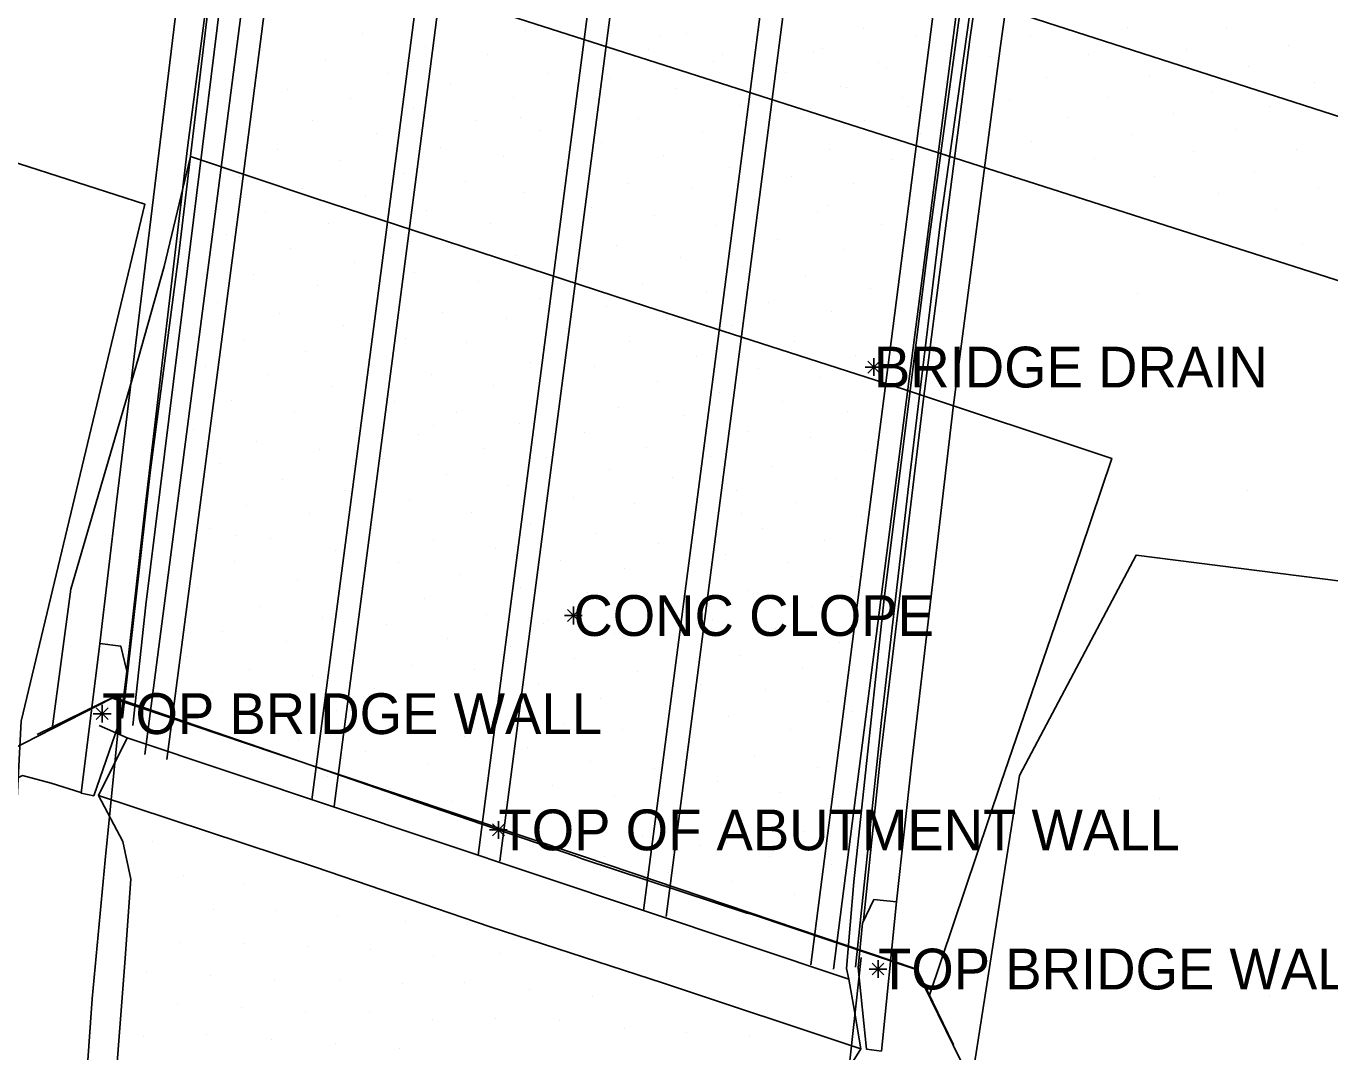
# Model space of a CAD drawing. Extents: x 1733582 to 1734070, y 467256 to 468256.
# Drawn here: x 1733813.9 to 1733871.5, y 467649 to 467694.3 of the extents above; entities that cross this region are included whole.
import ezdxf

# ---------------------------------------------------------------- set-up
doc = ezdxf.new("R2010")
doc.units = 0
for name, color, linetype in [('Default', 7, 'Continuous'), ('S_Bridge_Abutment_Bottom', 7, 'Continuous'), ('S_Bridge_Curb', 7, 'Continuous'), ('S_Bridge_Deck', 7, 'Continuous'), ('S_Bridge_ExpansionJoint', 7, 'Continuous'), ('S_Bridge_Parapet', 7, 'Continuous'), ('S_Bridge_Rail', 7, 'Continuous'), ('S_Bridge_Wingwall', 7, 'Continuous'), ('S_Ground_LevelString', 7, 'Continuous'), ('S_Ground_SpotElevation', 7, 'Continuous'), ('S_Guardrail_Beam', 7, 'Continuous'), ('S_Misc_MiscFeature', 7, 'Continuous'), ('S_Misc_MiscItems', 7, 'Continuous'), ('S_Roadway_Edge_Pavement', 7, 'Continuous'), ('S_Roadway_Painted_Lines', 7, 'Continuous'), ('S_Text', 7, 'Continuous'), ('S_Trees_Bush_Line', 7, 'Continuous')]:
    doc.layers.add(name, color=color, linetype=linetype)

# ---------------------------------------------------------------- blocks, each defined once
blk = doc.blocks.new('POINT_DISPLAY')
at = {"layer": 'Default'}
blk.add_line((0, 0), (0, 0), dxfattribs=at)

msp = doc.modelspace()

# ---------------------------------------------------------------- linework, layer by layer
at = {"layer": 'S_Bridge_Abutment_Bottom'}
for points in [[(1733853.787, 467651.451), (1733856.947, 467660.863), (1733859.499, 467668.329), (1733860.465, 467671.091), (1733861.843, 467675.202), (1733852.689, 467678.242), (1733841.297, 467681.912), (1733826.618, 467686.702), (1733821.169, 467688.527), (1733820, 467683.677), (1733818.858, 467679.602), (1733815.879, 467669.434), (1733815.061, 467663.265)], [(1733856.158, 467646.59), (1733853.195, 467652.663), (1733838.519, 467657.625), (1733824.913, 467662.193), (1733817.71, 467664.62), (1733811.826, 467661.611)]]:
    msp.add_lwpolyline(points, dxfattribs=at)
at = {"layer": 'S_Bridge_Curb'}
for points in [[(1733818.159, 467663.732), (1733819.385, 467674.582), (1733820.64, 467684.116), (1733822.243, 467697.564), (1733823.972, 467709.579), (1733825.87, 467722.342), (1733827.859, 467734.138), (1733830.216, 467748.192), (1733832.11, 467758.256), (1733834.51, 467770.45), (1733837.898, 467787.063), (1733840.865, 467800.549), (1733844.359, 467815.787), (1733847.831, 467829.289), (1733850.56, 467839.861), (1733853.05, 467849.061), (1733854.563, 467854.584)], [(1733850.525, 467652.736), (1733851.676, 467663.636), (1733852.883, 467674.082), (1733854.262, 467685.548), (1733855.565, 467694.75), (1733856.845, 467703.748), (1733858.974, 467717.399), (1733861.233, 467731.524), (1733863.482, 467743.881), (1733865.283, 467752.922), (1733867.113, 467762.582), (1733868.83, 467770.933), (1733871.654, 467784.015), (1733874.05, 467794.414), (1733876.107, 467803.265), (1733877.952, 467810.863), (1733879.709, 467817.89), (1733881.379, 467824.23), (1733883.522, 467832.303), (1733885.6, 467839.734), (1733886.897, 467844.023)]]:
    msp.add_lwpolyline(points, dxfattribs=at)
at = {"layer": 'S_Bridge_Deck'}
msp.add_line((1733817.139, 467663.409), (1733818.374, 467662.864), dxfattribs=at)
for points in [[(1733855.138, 467854.785), (1733853.086, 467847.693), (1733849.22, 467833.073), (1733845.482, 467818.291), (1733842.048, 467803.532), (1733838.704, 467788.663), (1733835.558, 467773.547), (1733832.728, 467759.072), (1733829.896, 467743.681), (1733827.379, 467728.743), (1733824.957, 467713.563), (1733822.869, 467698.529), (1733821.029, 467683.583), (1733819.201, 467668.729), (1733818.621, 467663.409)], [(1733886.549, 467844.629), (1733884.683, 467838.178), (1733882.551, 467830.444), (1733878.067, 467813.135), (1733874.221, 467797.292), (1733871.125, 467783.729), (1733866.753, 467762.871), (1733863.994, 467749.165), (1733860.716, 467731.07), (1733858.373, 467716.77), (1733855.935, 467700.728), (1733853.766, 467684.771), (1733851.796, 467669.015), (1733850.46, 467656.5), (1733850.135, 467652.683), (1733850.236, 467652.213)]]:
    msp.add_lwpolyline(points, dxfattribs=at)
at = {"layer": 'S_Bridge_ExpansionJoint'}
for points in [[(1733850.236, 467652.213), (1733818.374, 467662.864), (1733817.11, 467660.315), (1733826.68, 467657.156), (1733834.4, 467654.523), (1733842.051, 467652.036), (1733850.758, 467649.134), (1733850.483, 467650.79), (1733850.236, 467652.213)], [(1733817.11, 467660.315), (1733826.68, 467657.156), (1733834.4, 467654.523), (1733842.051, 467652.036), (1733850.758, 467649.134)]]:
    msp.add_lwpolyline(points, dxfattribs=at)
at = {"layer": 'S_Bridge_Parapet'}
for points in [[(1733816.907, 467660.305), (1733818.113, 467663.794), (1733818.35, 467665.811), (1733818.091, 467666.911), (1733817.169, 467667.027), (1733816.348, 467660.418), (1733816.907, 467660.305)], [(1733852.333, 467655.629), (1733851.341, 467655.722), (1733850.84, 467654.678), (1733850.65, 467652.713), (1733851.016, 467649.11), (1733851.669, 467649.029), (1733852.333, 467655.629)]]:
    msp.add_lwpolyline(points, dxfattribs=at)
at = {"layer": 'S_Bridge_Rail'}
for points in [[(1733818.359, 467665.855), (1733819.171, 467673.048), (1733821.039, 467688.917), (1733823.113, 467704.785), (1733825.46, 467720.602), (1733828.058, 467736.434), (1733830.845, 467752.168), (1733833.805, 467767.85), (1733837.016, 467783.594), (1733840.405, 467799.172), (1733844.065, 467814.724), (1733847.908, 467830.326), (1733851.933, 467845.769), (1733853.853, 467852.641)], [(1733886.303, 467841.899), (1733884.339, 467834.722), (1733880.236, 467819.247), (1733876.383, 467803.848), (1733872.741, 467788.157), (1733869.344, 467772.479), (1733866.194, 467756.807), (1733863.147, 467741.167), (1733860.402, 467725.353), (1733857.873, 467709.488), (1733855.573, 467693.7), (1733853.508, 467677.718), (1733851.616, 467661.907), (1733850.883, 467654.795)]]:
    msp.add_lwpolyline(points, dxfattribs=at)
at = {"layer": 'S_Bridge_Wingwall'}
msp.add_lwpolyline([(1733816.328, 467660.448), (1733815.01, 467660.86), (1733813.747, 467661.195), (1733812.317, 467660.528)], dxfattribs=at)
at = {"layer": 'S_Ground_LevelString'}
msp.add_lwpolyline([(1733853.787, 467651.451), (1733856.947, 467660.863), (1733859.499, 467668.329), (1733860.465, 467671.091), (1733861.843, 467675.202), (1733852.689, 467678.242), (1733841.297, 467681.912), (1733826.618, 467686.702), (1733821.169, 467688.527), (1733820, 467683.677), (1733818.858, 467679.602), (1733815.879, 467669.434), (1733815.061, 467663.265)], dxfattribs=at)
at = {"layer": 'S_Guardrail_Beam'}
for points in [[(1733807.383, 467564.54), (1733809.319, 467567.868), (1733810.292, 467569.832), (1733810.683, 467571.034), (1733811.12, 467573.524), (1733811.405, 467576.28), (1733812.386, 467588.95), (1733813.146, 467601.374), (1733813.995, 467613.961), (1733814.875, 467626.317), (1733815.844, 467638.741), (1733816.383, 467645.072), (1733816.822, 467651.337), (1733817.407, 467657.46), (1733818.079, 467664.272)], [(1733850.774, 467653.171), (1733849.7, 467643.369), (1733849.038, 467637.329), (1733848.501, 467631.188), (1733847.844, 467621.901), (1733847.266, 467609.259), (1733846.773, 467596.932), (1733846.395, 467584.271), (1733846.161, 467571.826), (1733846.092, 467559.57), (1733846.114, 467553.099), (1733846.071, 467546.973), (1733846.619, 467534.281), (1733847.23, 467525.758), (1733848.03, 467521.946), (1733848.441, 467520.58), (1733850.4, 467515.952)]]:
    msp.add_lwpolyline(points, dxfattribs=at)
at = {"layer": 'S_Misc_MiscFeature'}
for points in [[(1733819.146, 467662.128), (1733822.411, 467687.138), (1733825.625, 467712.064), (1733828.308, 467732.621), (1733831.184, 467747.947), (1733833.505, 467760.094), (1733835.806, 467771.99), (1733838.257, 467784.633), (1733839.477, 467789.916), (1733843.642, 467806.605), (1733849.69, 467830.62), (1733855.796, 467855.018)], [(1733820.122, 467661.91), (1733823.472, 467687.541), (1733826.672, 467712.367), (1733829.355, 467732.542), (1733832.44, 467748.988), (1733834.659, 467760.701), (1733836.916, 467772.404), (1733839.778, 467786.991), (1733844.946, 467807.685), (1733851.172, 467832.455), (1733856.733, 467854.727)], [(1733826.53, 467660.119), (1733830.278, 467688.775), (1733833.202, 467711.396), (1733835.635, 467730.109), (1733838.854, 467747.125), (1733841.053, 467758.65), (1733843.35, 467770.62), (1733845.821, 467783.336), (1733847.212, 467789.204), (1733851.47, 467806.186), (1733857.516, 467830.268), (1733863.15, 467852.64)], [(1733864.079, 467852.275), (1733858.131, 467828.607), (1733852.049, 467804.339), (1733847.192, 467785.066), (1733844.207, 467769.696), (1733841.988, 467758.102), (1733839.394, 467744.549), (1733836.696, 467730.312), (1733833.835, 467708.583), (1733831.31, 467688.992), (1733827.509, 467659.844)], [(1733852.432, 467852.088), (1733847.956, 467835.582), (1733844.668, 467822.664), (1733840.962, 467807.205), (1733837.376, 467791.545), (1733834.11, 467775.918), (1733831.093, 467760.248), (1733828.17, 467744.438), (1733825.424, 467728.718), (1733822.802, 467711.353), (1733820.741, 467696.705), (1733817.897, 467673.275), (1733817.169, 467667.027)], [(1733833.862, 467657.682), (1733837.178, 467683.156), (1733840.254, 467706.86), (1733843.003, 467727.895), (1733846.149, 467744.535), (1733848.346, 467756.071), (1733850.647, 467768.07), (1733853.573, 467783.047), (1733858.608, 467802.95), (1733864.671, 467827.038), (1733870.472, 467850.181)], [(1733871.393, 467849.822), (1733865.695, 467826.963), (1733859.504, 467802.42), (1733854.508, 467782.647), (1733851.621, 467767.768), (1733849.286, 467755.703), (1733847.085, 467744.185), (1733843.99, 467727.733), (1733841.143, 467705.862), (1733838.187, 467683.149), (1733834.828, 467657.424)], [(1733841.162, 467655.238), (1733844.601, 467681.503), (1733847.732, 467705.748), (1733850.338, 467725.565), (1733853.469, 467742.079), (1733855.705, 467753.836), (1733857.987, 467765.604), (1733860.885, 467780.409), (1733865.914, 467800.487), (1733872.136, 467825.216), (1733877.778, 467847.684)], [(1733878.753, 467847.484), (1733873.086, 467824.941), (1733866.9, 467800.334), (1733861.829, 467780.055), (1733858.912, 467765.093), (1733856.608, 467753.207), (1733854.359, 467741.368), (1733851.322, 467725.26), (1733848.676, 467705.17), (1733845.544, 467680.934), (1733842.168, 467654.979)], [(1733848.559, 467652.836), (1733852.024, 467679.791), (1733855.066, 467703.463), (1733857.598, 467722.922), (1733860.883, 467740.131), (1733863.02, 467751.281), (1733865.314, 467763.253), (1733868.31, 467778.566), (1733873.148, 467797.76), (1733879.142, 467821.53), (1733885.249, 467845.685)], [(1733849.555, 467652.651), (1733852.726, 467677.347), (1733855.925, 467702.233), (1733858.601, 467722.747), (1733863.855, 467750.228), (1733866.106, 467762.026), (1733869.19, 467777.948), (1733873.963, 467796.905), (1733880.016, 467820.978), (1733886.27, 467845.573)], [(1733887.367, 467840.604), (1733883.605, 467826.737), (1733879.636, 467811.346), (1733877.727, 467803.516), (1733874.188, 467788.265), (1733870.678, 467772.276), (1733867.49, 467756.558), (1733864.467, 467740.84), (1733861.741, 467725.141), (1733859.155, 467709.272), (1733856.917, 467693.32), (1733854.838, 467677.445), (1733853.015, 467661.799), (1733852.333, 467655.629)], [(1733854.86, 467649.309), (1733853.253, 467652.627), (1733845.934, 467655.075), (1733845.734, 467655.129), (1733838.461, 467657.528), (1733838.16, 467657.638), (1733831.19, 467660.019), (1733830.898, 467660.13), (1733823.798, 467662.588), (1733823.664, 467662.635), (1733817.77, 467664.653), (1733814.402, 467663.011)], [(1733854.86, 467649.309), (1733853.253, 467652.627), (1733845.934, 467655.075), (1733845.734, 467655.129), (1733838.461, 467657.528), (1733838.16, 467657.638), (1733831.19, 467660.019), (1733830.898, 467660.13), (1733823.798, 467662.588), (1733823.664, 467662.635), (1733817.77, 467664.653), (1733814.402, 467663.011)]]:
    msp.add_lwpolyline(points, dxfattribs=at)
at = {"layer": 'S_Misc_MiscItems'}
for p, q in [((1733851.602, 467678.971), (1733851.078, 467679.495)), ((1733851.602, 467679.495), (1733851.078, 467678.971)), ((1733851.34, 467679.626), (1733851.34, 467678.84)), ((1733851.733, 467679.233), (1733850.947, 467679.233)), ((1733838.074, 467668.655), (1733838.074, 467667.869)), ((1733838.467, 467668.262), (1733837.681, 467668.262)), ((1733838.336, 467668), (1733837.812, 467668.524)), ((1733838.336, 467668.524), (1733837.812, 467668)), ((1733817.531, 467663.668), (1733817.007, 467664.192)), ((1733817.531, 467664.192), (1733817.007, 467663.668)), ((1733817.269, 467664.323), (1733817.269, 467663.537)), ((1733817.662, 467663.93), (1733816.876, 467663.93)), ((1733835.156, 467658.798), (1733834.37, 467658.798)), ((1733835.025, 467658.536), (1733834.501, 467659.06)), ((1733835.025, 467659.06), (1733834.501, 467658.536)), ((1733834.763, 467659.191), (1733834.763, 467658.405)), ((1733851.523, 467653.047), (1733851.523, 467652.261)), ((1733851.916, 467652.654), (1733851.13, 467652.654)), ((1733851.785, 467652.392), (1733851.261, 467652.916)), ((1733851.785, 467652.916), (1733851.261, 467652.392))]:
    msp.add_line(p, q, dxfattribs=at)
at = {"layer": 'S_Roadway_Edge_Pavement'}
for points in [[(1733586.071, 467770.749), (1733667.71, 467746.624), (1733748.731, 467721.817), (1733825.312, 467697.928), (1733923.075, 467666.68), (1733975.856, 467650.261), (1734036.534, 467629.484)], [(1733811.638, 467569.582), (1733812.734, 467577.021), (1733813.757, 467585.557), (1733814.613, 467595.624), (1733815.23, 467608.506), (1733815.639, 467618.757), (1733816.86, 467632.87), (1733817.506, 467642.976), (1733818.267, 467652.925), (1733818.527, 467656.619), (1733818.179, 467658.292), (1733817.11, 467660.315)], [(1733850.758, 467649.134), (1733849.614, 467647.295), (1733848.657, 467641.484), (1733847.905, 467635.887), (1733847.075, 467626.71), (1733846.566, 467614.147), (1733846.014, 467599.792), (1733845.743, 467588.926), (1733845.43, 467578.906), (1733845.032, 467567.549), (1733844.857, 467556.393), (1733844.807, 467544.75)]]:
    msp.add_lwpolyline(points, dxfattribs=at)
at = {"layer": 'S_Roadway_Painted_Lines'}
msp.add_lwpolyline([(1733588.359, 467777.226), (1733663.015, 467755.304), (1733706.127, 467742.598), (1733754.684, 467727.868), (1733796.902, 467714.64), (1733820.732, 467706.9), (1733859.007, 467694.431), (1733908.923, 467678.371), (1733969.097, 467659.316), (1734007.606, 467646.911), (1734038.438, 467636.916)], dxfattribs=at)
at = {"layer": 'S_Trees_Bush_Line'}
for points in [[(1733782.388, 467697.52), (1733808.894, 467689.72), (1733819.157, 467686.424), (1733813.691, 467663.605), (1733812.871, 467647.725), (1733812.189, 467625.431), (1733809.644, 467598.992), (1733806.301, 467596.783), (1733800.72, 467597.637), (1733791.368, 467597.96), (1733786.918, 467595.259), (1733783.903, 467589.747), (1733782.156, 467575.789)], [(1733870.477, 467392.586), (1733863.304, 467396.173), (1733858.349, 467437.262), (1733858.746, 467475.792), (1733855.851, 467518.527), (1733851.718, 467552.624), (1733854.117, 467581.29), (1733854.359, 467608.625), (1733855.003, 467643.492), (1733857.771, 467661.204), (1733862.914, 467670.922), (1733887.365, 467667.82), (1733924.768, 467650.09), (1734031.288, 467613.464)]]:
    msp.add_lwpolyline(points, dxfattribs=at)

# ---------------------------------------------------------------- block references
at = {"layer": 'S_Ground_SpotElevation'}
for p in [(1733822.152, 467694.119), (1733828.75, 467693.942), (1733835.949, 467694.115), (1733843.055, 467693.977), (1733846.288, 467694.082), (1733850.895, 467694.196), (1733858.255, 467693.892), (1733862.534, 467694.228), (1733866.891, 467694.202), (1733831.53, 467693.374), (1733838.721, 467693.546), (1733841.939, 467693.837), (1733845.963, 467693.628), (1733849.083, 467693.301), (1733853.16, 467693.847), (1733853.509, 467693.463), (1733869.628, 467693.447), (1733824.298, 467693.212), (1733827.126, 467692.788), (1733834.264, 467693.031), (1733841.376, 467693.276), (1733844.677, 467693.055), (1733848.681, 467693.172), (1733856.491, 467692.953), (1733860.821, 467693.056), (1733865.145, 467693.255), (1733829.877, 467692.215), (1733836.957, 467692.186), (1733844.276, 467692.707), (1733847.426, 467692.249), (1733851.521, 467692.667), (1733851.896, 467692.439), (1733867.898, 467692.52), (1733832.628, 467691.688), (1733839.678, 467691.979), (1733847.114, 467692.07), (1733849.87, 467691.601), (1733850.123, 467691.57), (1733854.512, 467691.779), (1733858.941, 467692.025), (1733863.501, 467692.104), (1733870.785, 467691.806), (1733825.431, 467691.496), (1733828.23, 467691.096), (1733835.414, 467691.127), (1733842.58, 467691.512), (1733852.613, 467691.144), (1733857.335, 467691.004), (1733861.71, 467691.14), (1733866.229, 467691.35), (1733823.753, 467690.471), (1733830.998, 467690.672), (1733838.231, 467690.701), (1733845.424, 467690.774), (1733852.863, 467690.724), (1733868.818, 467690.749), (1733826.541, 467690.131), (1733833.785, 467690.121), (1733835.754, 467690.247), (1733840.958, 467690.197), (1733848.157, 467690.237), (1733850.933, 467690.126), (1733855.446, 467690.045), (1733859.915, 467690.243), (1733864.559, 467690.412), (1733829.401, 467689.528), (1733836.608, 467689.688), (1733843.784, 467689.615), (1733853.386, 467689.56), (1733862.706, 467689.484), (1733867.332, 467689.728), (1733824.989, 467688.834), (1733832.187, 467688.945), (1733839.305, 467689.151), (1733846.594, 467689.181), (1733849.388, 467688.831), (1733858.289, 467689.214), (1733865.433, 467688.732), (1733869.985, 467688.832), (1733827.767, 467688.334), (1733834.976, 467688.515), (1733842.042, 467688.59), (1733852.118, 467688.418), (1733861.077, 467688.438), (1733823.325, 467687.654), (1733830.555, 467687.798), (1733837.678, 467687.86), (1733844.96, 467688.041), (1733847.703, 467687.65), (1733863.736, 467687.636), (1733868.149, 467687.885), (1733826.127, 467687.129), (1733833.29, 467687.443), (1733840.442, 467687.338), (1733843.265, 467687.16), (1733850.425, 467687.345), (1733870.978, 467687.124), (1733828.886, 467686.778), (1733835.914, 467686.945), (1733846.085, 467686.616), (1733852.939, 467686.491), (1733866.569, 467686.894), (1733824.478, 467686.093), (1733831.601, 467686.15), (1733838.872, 467686.283), (1733841.668, 467685.943), (1733848.87, 467686.1), (1733849.356, 467686.375), (1733869.131, 467686.199), (1733827.271, 467685.567), (1733834.409, 467685.585), (1733837.248, 467685.268), (1733844.409, 467685.468), (1733851.689, 467685.524), (1733822.763, 467685.078), (1733829.994, 467684.902), (1733847.101, 467684.853), (1733825.604, 467684.482), (1733832.705, 467684.625), (1733835.57, 467684.175), (1733839.979, 467684.617), (1733842.82, 467684.092), (1733850.009, 467684.42), (1733852.653, 467684.098), (1733870.276, 467684.651), (1733828.415, 467683.858), (1733838.404, 467683.593), (1733845.538, 467683.694), (1733823.943, 467683.331), (1733831.061, 467683.423), (1733833.903, 467682.996), (1733848.325, 467683.235), (1733826.768, 467682.821), (1733841.13, 467682.916), (1733843.963, 467682.555), (1733851.195, 467682.719), (1733862.958, 467682.503), (1733822.358, 467682.081), (1733829.461, 467682.209), (1733836.585, 467682.239), (1733839.514, 467681.912), (1733846.692, 467682.069), (1733825.098, 467681.614), (1733832.31, 467681.642), (1733835.111, 467681.382), (1733842.187, 467681.321), (1733849.475, 467681.708), (1733827.93, 467681.088), (1733837.828, 467680.953), (1733845.056, 467681.051), (1733852.293, 467681.092), (1733823.49, 467680.395), (1733830.64, 467680.482), (1733833.347, 467680.337), (1733840.543, 467680.356), (1733847.832, 467680.382), (1733826.258, 467679.909), (1733829.012, 467679.58), (1733843.486, 467679.711), (1733850.547, 467679.726), (1733821.842, 467679.255), (1733831.825, 467678.92), (1733836.168, 467679.442), (1733839.014, 467679.237), (1733846.24, 467679.152), (1733824.625, 467678.889), (1733827.416, 467678.367), (1733834.543, 467678.429), (1733841.795, 467678.599), (1733848.955, 467678.764), (1733851.734, 467678.442), (1733837.407, 467678.016), (1733844.53, 467678.112), (1733822.998, 467677.737), (1733825.768, 467677.226), (1733830.174, 467677.698), (1733832.933, 467677.229), (1733840.043, 467677.439), (1733847.318, 467677.695), (1733850.17, 467677.264), (1733831.882, 467676.645), (1733835.711, 467676.729), (1733842.926, 467677.08), (1733821.287, 467676.479), (1733828.505, 467676.549), (1733831.237, 467676.242), (1733838.564, 467676.33), (1733845.753, 467676.382), (1733848.521, 467676.141), (1733824.075, 467675.967), (1733826.88, 467675.577), (1733834.104, 467675.658), (1733841.296, 467675.696), (1733822.463, 467674.954), (1733829.669, 467675.18), (1733836.891, 467675.255), (1733844.137, 467675.301), (1733851.243, 467675.446), (1733832.472, 467674.497), (1733839.668, 467674.699), (1733842.457, 467674.339), (1733846.884, 467674.864), (1733820.847, 467673.836), (1733825.217, 467674.289), (1733827.989, 467673.784), (1733835.173, 467674.021), (1733845.261, 467673.769), (1733849.677, 467674.299), (1733867.823, 467673.766), (1733830.845, 467673.368), (1733838.063, 467673.479), (1733840.79, 467673.219), (1733847.891, 467673.248), (1733823.626, 467673.131), (1733826.437, 467672.751), (1733833.589, 467672.826), (1733843.616, 467672.651), (1733845.484, 467672.773), (1733850.802, 467672.626), (1733822.006, 467672.091), (1733829.167, 467672.111), (1733836.194, 467672.29), (1733846.425, 467672.105), (1733823.145, 467671.78), (1733824.721, 467671.684), (1733831.892, 467671.629), (1733839.074, 467671.9), (1733841.841, 467671.452), (1733849.174, 467671.576), (1733827.559, 467671.122), (1733834.646, 467671.233), (1733844.784, 467670.964), (1733823.101, 467670.627), (1733830.349, 467670.61), (1733837.511, 467670.68), (1733840.318, 467670.335), (1733847.521, 467670.585), (1733825.89, 467669.85), (1733833.093, 467670.08), (1733850.343, 467669.998), (1733821.459, 467669.464), (1733828.7, 467669.481), (1733835.722, 467669.503), (1733838.679, 467669.28), (1733843.098, 467669.688), (1733845.808, 467669.383), (1733824.224, 467668.643), (1733831.509, 467668.998), (1733841.502, 467668.662), (1733848.607, 467668.64), (1733827.008, 467668.194), (1733834.217, 467668.309), (1733836.979, 467668.085), (1733844.229, 467668.079), (1733822.586, 467667.562), (1733829.834, 467667.874), (1733836.747, 467667.908), (1733839.869, 467667.485), (1733846.986, 467667.691), (1733825.41, 467667.098), (1733832.527, 467667.236), (1733835.279, 467666.891), (1733842.611, 467667.024), (1733849.831, 467667.087), (1733820.994, 467666.455), (1733828.219, 467666.703), (1733838.132, 467666.374), (1733845.394, 467666.511), (1733823.756, 467665.895), (1733830.977, 467666.066), (1733833.696, 467665.899), (1733840.886, 467665.799), (1733848.18, 467665.942), (1733826.543, 467665.612), (1733836.551, 467665.199), (1733843.749, 467665.23), (1733822.152, 467664.914), (1733829.296, 467665.028), (1733832.123, 467664.569), (1733839.26, 467664.617), (1733846.537, 467665.008), (1733824.905, 467664.324), (1733827.603, 467664.084), (1733834.899, 467664.176), (1733842.137, 467664.318), (1733849.348, 467664.453), (1733850.349, 467664.037), (1733820.48, 467663.649), (1733837.677, 467663.481), (1733844.923, 467663.815), (1733823.31, 467663.207), (1733828.01, 467663.043), (1733830.49, 467663.344), (1733833.267, 467662.9), (1733840.259, 467663.215), (1733847.673, 467663.211), (1733850.115, 467662.925), (1733825.933, 467662.758), (1733828.885, 467662.274), (1733836.054, 467662.435), (1733843.19, 467662.481), (1733831.623, 467661.688), (1733838.822, 467661.816), (1733846.058, 467662.054), (1733827.196, 467661.16), (1733834.356, 467661.16), (1733841.646, 467661.497), (1733848.866, 467661.563), (1733830, 467660.628), (1733837.157, 467660.768), (1733844.44, 467660.925), (1733832.732, 467660.068), (1733839.875, 467660.325), (1733847.224, 467660.443), (1733863.951, 467660.165), (1733835.541, 467659.637), (1733842.779, 467659.759), (1733849.781, 467659.828), (1733838.154, 467659.33), (1733841.612, 467659.171), (1733845.55, 467659.227), (1733819.476, 467658.269), (1733841.106, 467658.571), (1733848.297, 467658.724), (1733836.725, 467658.016), (1733839.439, 467657.634), (1733843.648, 467658.11), (1733846.725, 467657.626), (1733849.49, 467657.279), (1733820.877, 467656.796), (1733842.276, 467656.923), (1733845.076, 467656.523), (1733823.537, 467656.428), (1733847.835, 467655.93), (1733822.163, 467655.276), (1733824.976, 467655.227), (1733827.64, 467654.971), (1733830.644, 467654.763), (1733846.234, 467654.832), (1733848.97, 467654.383), (1733820.713, 467653.842), (1733823.545, 467653.802), (1733826.322, 467653.647), (1733829.126, 467653.519), (1733831.913, 467653.198), (1733834.842, 467653.332), (1733819.245, 467652.548), (1733822.033, 467652.391), (1733824.863, 467652.214), (1733827.73, 467652.165), (1733830.515, 467652.016), (1733833.275, 467652.04), (1733836.15, 467651.733), (1733838.925, 467651.461), (1733868.816, 467651.428), (1733820.594, 467651.139), (1733823.423, 467650.966), (1733826.236, 467650.757), (1733829.067, 467650.734), (1733831.832, 467650.419), (1733834.627, 467650.455), (1733837.445, 467650.39), (1733819.096, 467649.696), (1733821.889, 467649.757), (1733840.333, 467650.037), (1733843.087, 467649.837), (1733845.868, 467649.705), (1733824.745, 467649.522), (1733827.572, 467649.357), (1733830.404, 467649.151)]:
    msp.add_blockref('POINT_DISPLAY', p, dxfattribs=at)

# ---------------------------------------------------------------- texts
at = {"layer": 'S_Text'}
for s, p in [('BRIDGE DRAIN', (1733851.34, 467678.333)), ('CONC CLOPE', (1733838.074, 467667.362)), ('TOP BRIDGE WALL', (1733817.269, 467663.03)), ('TOP OF ABUTMENT WALL', (1733834.763, 467657.898)), ('TOP BRIDGE WALL', (1733851.523, 467651.754))]:
    msp.add_text(s, height=1.8, dxfattribs=at).set_placement(p)

doc.saveas('drawing.dxf')
